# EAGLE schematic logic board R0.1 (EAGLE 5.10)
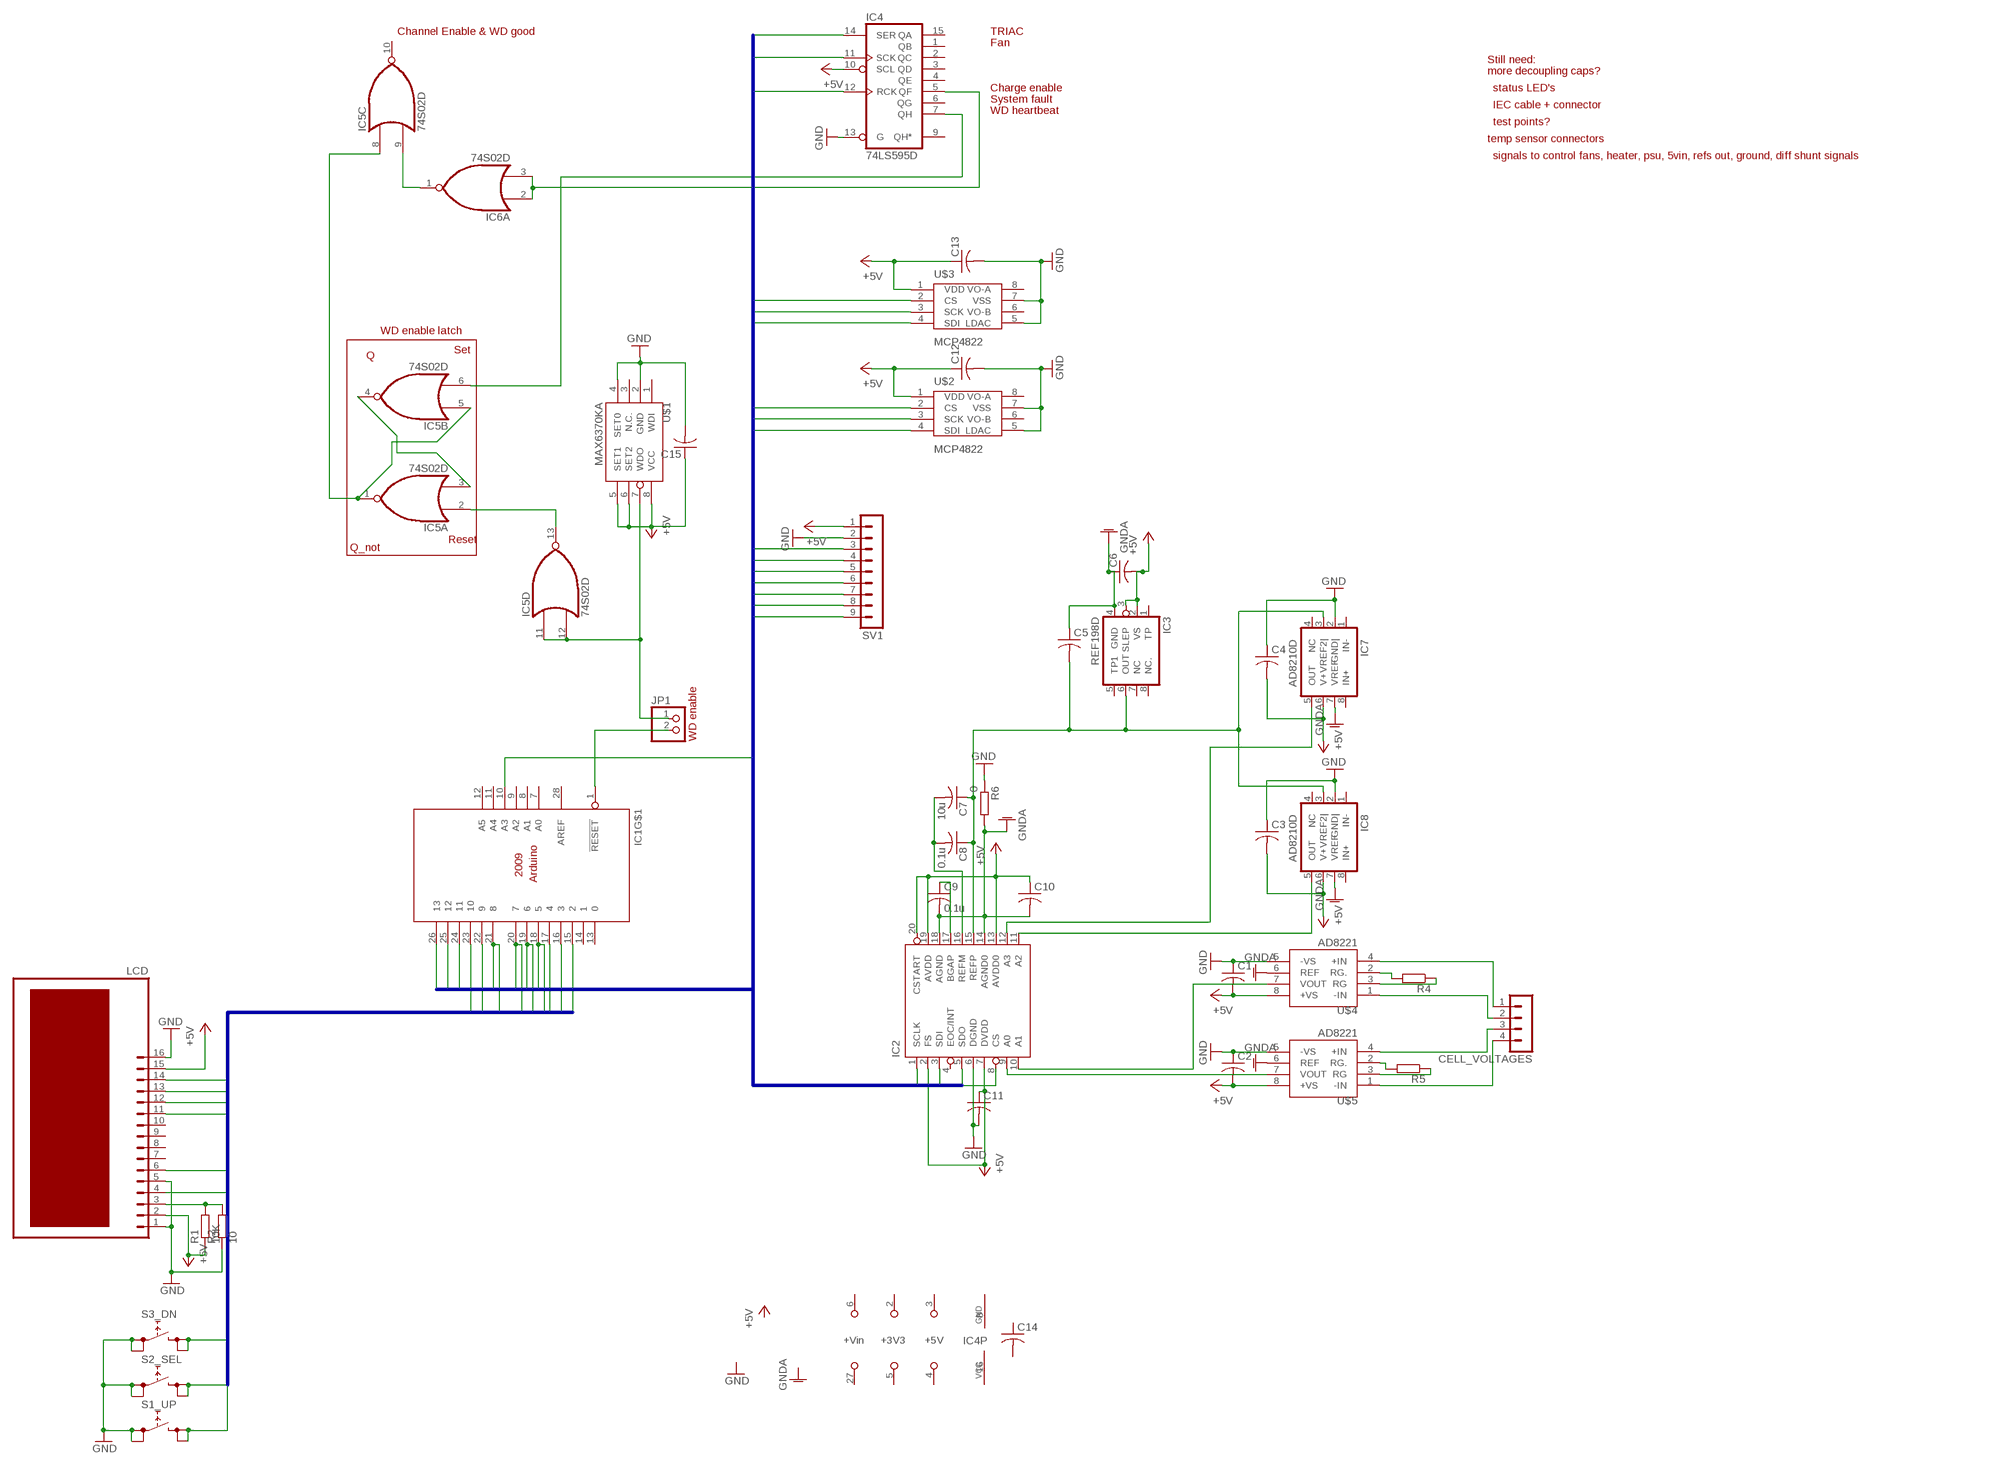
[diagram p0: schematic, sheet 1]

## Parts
C1  C-USC0805  [C0805]
C2  C-USC0805  [C0805]
C3  C-USC0805  [C0805]
C4  C-USC0805  [C0805]
C5  C-USC0805  [C0805]
C6  C-USC0805  [C0805]
C7  10u  C-USC0805  [C0805]
C8  0.1u  C-USC0805  [C0805]
C9  0.1u  C-USC0805  [C0805]
C10  C-USC0805  [C0805]
C11  C-USC0805  [C0805]
C12  C-USC0805  [C0805]
C13  C-USC0805  [C0805]
C14  C-USC0805  [C0805]
C15  C-USC0805  [C0805]
CELL_VOLTAGES  4PIN-HORIZONTAL  [4PIN_HORIZONTAL]
IC1  ARDUINO2009_20  [ARDUINO2009]
IC2  TLC3544D  [SO20W]
IC3  REF198D  [SO08]
IC4  74LS595D  [SO16]
IC5  74S02D  [SO14]
IC6  74S02D  [SO14]
IC7  AD8210D  [SO08]
IC8  AD8210D  [SO08]
JP1  PINHD-1X2  [1X02]
LCD  HDM16216L-5  [HDM16216L-5]
R1  10K  R-EU_R0805  [R0805]
R2  10  R-EU_R0805  [R0805]
R4  R-EU_R0805  [R0805]
R5  R-EU_R0805  [R0805]
R6  0  R-EU_R0805  [R0805]
S1_UP  REKN  [REKN]
S2_SEL  REKN  [REKN]
S3_DN  REKN  [REKN]
SV1  MA09-1  [MA09-1]
U$1  MAX6370KA  [SOT23-8]
U$2  MCP4822  [SO08]
U$3  MCP4822  [SO08]
U$4  AD8221  [SO08]
U$5  AD8221  [SO08]

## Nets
595_LATCH: IC1.10(A3) IC4.12(RCK)
+5V: C1.2 C2.2 C3.2 C4.2 C6.2 C10.1 C11.1 C12.1 C13.1 C15.1 IC2.2(FS) IC2.7(DVDD) IC2.13(AVDD0) IC2.19(AVDD) IC2.20(CSTART) IC3.2(VS) IC3.3(SLEP) IC4.10(SCL) IC7.6(V+) IC8.6(V+) LCD.2 LCD.15 R1.1 SV1.1 U$1.5(SET1) U$1.6(SET2) U$1.8(VCC) U$2.1(VDD) U$3.1(VDD) U$4.8(+VS) U$5.8(+VS)
GND: C1.1 C2.1 C3.1 C4.1 C11.2 C12.2 C13.2 C15.2 IC2.6(DGND) IC4.13(G) IC7.2(GND|) IC8.2(GND|) LCD.1 LCD.5 LCD.16 R2.1 R6.1 S1_UP.1A S1_UP.1B S2_SEL.1A S2_SEL.1B S3_DN.1A S3_DN.1B SV1.2 U$1.2(GND) U$1.4(SET0) U$2.5(LDAC) U$2.7(VSS) U$3.5(LDAC) U$3.7(VSS) U$4.5(-VS) U$5.5(-VS)
GNDA: C5.1 C6.1 C9.2 C10.2 IC2.14(AGND0) IC2.18(AGND) IC3.4(GND) IC7.7(VREF) IC8.7(VREF) R6.2 U$4.6(REF) U$5.6(REF)
LCD_D4/CS_ADC1: IC1.18 IC2.8(CS) LCD.11 SV1.8
LCD_D5/CS_DAC1: IC1.19 LCD.12 SV1.6 U$2.2(CS)
LCD_D6/CS_DAC2: IC1.20 LCD.13 SV1.7 U$3.2(CS)
LCD_D7/CS_AUX: IC1.21 LCD.14 SV1.9
LCD_ENABLE: IC1.23 LCD.6
LCD_RS: IC1.22 LCD.4
MISO: IC1.25 IC2.5(SDO) SV1.5
MOSI: IC1.24 IC2.3(SDI) IC4.14(SER) SV1.4 U$2.4(SDI) U$3.4(SDI)
N$1: LCD.3 R1.2 R2.2
N$2: R4.2 U$4.2(RG.)
N$3: R4.1 U$4.3(RG)
N$4: R5.2 U$5.2(RG.)
N$5: R5.1 U$5.3(RG)
N$6: CELL_VOLTAGES.1 U$4.4(+IN)
N$7: CELL_VOLTAGES.2 U$4.1(-IN)
N$8: CELL_VOLTAGES.3 U$5.4(+IN)
N$9: CELL_VOLTAGES.4 U$5.1(-IN)
N$10: C5.2 C7.1 C8.1 IC2.15(REFP) IC3.6(OUT) IC7.3(VREF2|) IC8.3(VREF2|)
N$11: C7.2 C8.2 IC2.16(REFM)
N$12: IC4.5(QF) IC6.2(A:I0) IC6.3(A:I1)
N$13: C9.1 IC2.17(BGAP)
N$14: IC2.12(A3) IC7.5(OUT)
N$15: IC2.11(A2) IC8.5(OUT)
N$16: IC2.10(A1) U$4.7(VOUT)
N$17: IC2.9(A0) U$5.7(VOUT)
N$18: IC1.1(!RESET) JP1.2
N$19: IC5.1(A:O) IC5.5(B:I0) IC5.8(C:I0)
N$20: IC5.3(A:I1) IC5.4(B:O)
N$21: IC5.11(D:I0) IC5.12(D:I1) JP1.1 U$1.7(WDO)
N$22: IC5.9(C:I1) IC6.1(A:O)
N$23: IC4.7(QH) IC5.6(B:I1)
N$24: IC5.2(A:I0) IC5.13(D:O)
PB_DN: IC1.17 S3_DN.2A S3_DN.2B
PB_SEL: IC1.16 S2_SEL.2A S2_SEL.2B
PB_UP: IC1.15 S1_UP.2A S1_UP.2B
SCK: IC1.26 IC2.1(SCLK) IC4.11(SCK) SV1.3 U$2.3(SCK) U$3.3(SCK)
Unconnected: C14.1 C14.2 IC1.7(A0) IC1.8(A1) IC1.9(A2) IC1.11(A4) IC1.12(A5) IC1.13 IC1.14 IC1.28(AREF) IC2.4(EOC/INT) IC3.1(TP) IC3.7(NC) IC3.8(NC.) IC4.1(QB) IC4.2(QC) IC4.3(QD) IC4.4(QE) IC4.6(QG) IC4.9(QH*) IC4.15(QA) IC5.10(C:O) IC6.4(B:O) IC6.5(B:I0) IC6.6(B:I1) IC6.8(C:I0) IC6.9(C:I1) IC6.10(C:O) IC6.11(D:I0) IC6.12(D:I1) IC6.13(D:O) IC7.1(IN-) IC7.8(IN+) IC8.1(IN-) IC8.8(IN+) LCD.7 LCD.8 LCD.9 LCD.10 U$1.1(WDI) U$1.3(N.C.) U$2.6(VO-B) U$2.8(VO-A) U$3.6(VO-B) U$3.8(VO-A)

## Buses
MOSI,MISO,SCK,LCD_D5/CS_DAC1,LCD_D6/CS_DAC2,LCD_D4/CS_ADC1,595_LATCH,LCD_D7/CS_AUX
LCD_D7/CS_AUX,LCD_D5/CS_DAC1,LCD_D6/CS_DAC2,LCD_D4/CS_ADC1,LCD_RS,LCD_ENABLE,PB_DN,PB_SEL,PB_UP

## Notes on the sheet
- Channel Enable & WD good | TRIAC
- Fan
- Still need:
- more decoupling caps?
- Charge enable | status LED's
- System fault
- IEC cable + connector
- WD heartbeat
- test points?
- temp sensor connectors
- signals to control fans, heater, psu, 5vin, refs out, ground, diff shunt signals
- WD enable latch
- Set
- Q
- Q_not | Reset
- WD enable

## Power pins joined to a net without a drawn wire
+3V3: IC1.2(+3V3)
+5V: IC1.3(+5V)
+VIN: IC1.6(+VIN)
GND: IC1.4(GND) IC1.5(GND) IC1.27(GND) IC4.8(GND) IC5.7(P:GND) IC6.7(P:GND)
NC: IC7.4(NC) IC8.4(NC)
TP1: IC3.5(TP1)
VCC: IC4.16(VCC) IC5.14(P:VCC) IC6.14(P:VCC)

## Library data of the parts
C1-C15 = rcl:C-US: CAPACITOR, American symbol
CELL_VOLTAGES = NEWPARTS:4PIN-HORIZONTAL: PIN HEADER
IC1 = arduino:ARDUINO2009_2: The Arduino Duemilanove ("2009") is a microcontroller board based on the ATmega168 or ATmega328. - 14 digital input/output pins (of which 6 can be used as PWM outputs) - 6 analog inputs, a 16 MHz crystal oscillator - USB connection - power jack - ISP header - reset button It contains everything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
IC2 = NEWPARTS:TLC3544: A/D CONVERTER
IC3 = NEWPARTS:REF198: Precision Micropower, Low Dropout Voltage References
IC4 = 74xx-us:74*595: 8-bit SHIFT REGISTER, output latch
IC5 IC6 = 74xx-us:74*02: Quad 2-input NOR gate
IC7 IC8 = NEWPARTS:AD8210: High Voltage, Bidirectional Current Shunt Monitor
JP1 = pinhead:PINHD-1X2: PIN HEADER
LCD = NEWPARTS:HDM16216L-5: PIN HEADER
R1 R2 R4-R6 = rcl:R-EU_: RESISTOR, European symbol
S1_UP S2_SEL S3_DN = NEWPARTS:REKN: PUSH SWITCH ITT-Cannon-Cannon
SV1 = con-lstb:MA09-1: PIN HEADER
U$1 = NEWPARTS:MAX6370KA
U$2 U$3 = NEWPARTS:MCP4822
U$4 U$5 = NEWPARTS:AD8221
